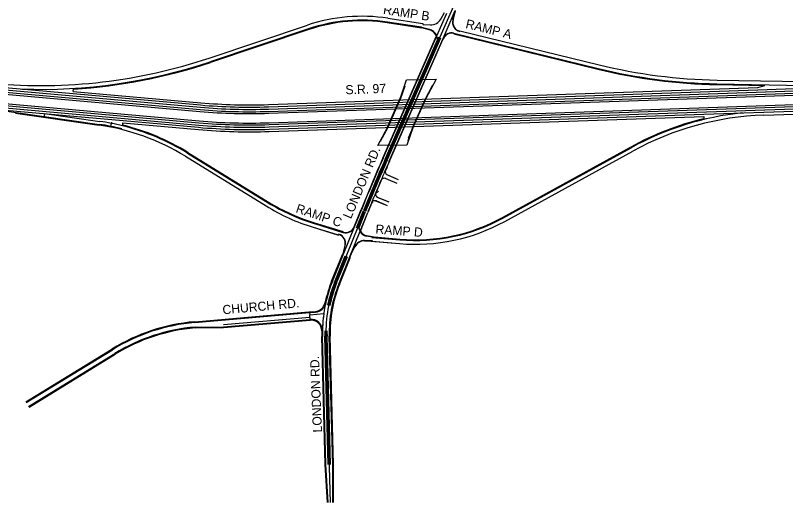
# Model space of a CAD drawing. Extents: x 2315515 to 2326910, y 758186 to 762794.
# Drawn here: x 2318941 to 2323003, y 758186 to 760752 of the extents above; entities that cross this region are included whole.
import ezdxf

# ---------------------------------------------------------------- set-up
doc = ezdxf.new("R2010")
doc.units = 0
for name, color, linetype in [('_CIVIL_CONSTRUCTION', 7, 'Continuous'), ('Bridge_Abutment', 7, 'Continuous'), ('Bridge_Bearing', 7, 'Continuous'), ('Bridge_Deck', 7, 'Continuous'), ('Clipping_Shape', 7, 'Continuous'), ('Default', 7, 'Continuous'), ('Draft_Corr_Final', 7, 'Continuous'), ('Draft_Corr_Range_Final', 7, 'Continuous'), ('E_Terrain_Exterior', 7, 'Continuous'), ('Pavement Marking Yellow', 7, 'Continuous'), ('Road_Curb_Face', 7, 'Continuous'), ('TL_Base Extension Sub', 7, 'Continuous'), ('TL_End Condition Ditch In', 7, 'Continuous'), ('TL_End Condition Ditch Out', 7, 'Continuous'), ('TL_Pavement Centerline', 7, 'Continuous'), ('TL_Pavement Centerline Sub', 7, 'Continuous')]:
    doc.layers.add(name, color=color, linetype=linetype)

msp = doc.modelspace()

# ---------------------------------------------------------------- linework, layer by layer
at = {"layer": '_CIVIL_CONSTRUCTION'}
for p, q in [((2315524.7, 760646.8), (2319915.4, 760256.1)), ((2315518.5, 760577.1), (2319909.2, 760186.4)), ((2320276.5, 760246.3), (2324006, 760375.3)), ((2320278.9, 760176.4), (2324008.4, 760305.3))]:
    msp.add_line(p, q, dxfattribs=at)
for radius in [2931, 3001]:
    msp.add_arc((2320175.2, 763175.6), radius, 264.9144, 271.9805, dxfattribs=at)
at = {"layer": 'Bridge_Abutment'}
for p, q in [((2320970, 760308.5), (2320994, 760379.5)), ((2321103.2, 760313.3), (2321141.6, 760383.5)), ((2320904.4, 760159.2), (2320970, 760308.5)), ((2321037.2, 760163.2), (2321103.2, 760313.3)), ((2320866, 760089.1), (2320904.4, 760159.2)), ((2321013.2, 760092.1), (2321037.2, 760163.2))]:
    msp.add_line(p, q, dxfattribs=at)
at = {"layer": 'Bridge_Bearing'}
for p, q in [((2320994, 760379.5), (2320970, 760308.5)), ((2321141.6, 760383.5), (2321103.2, 760313.3)), ((2320904.4, 760159.2), (2320970, 760308.5)), ((2321037.2, 760163.2), (2321103.2, 760313.3)), ((2320866, 760089.1), (2320904.4, 760159.2)), ((2321013.2, 760092.1), (2321037.2, 760163.2))]:
    msp.add_line(p, q, dxfattribs=at)
at = {"layer": 'Bridge_Deck'}
for p, q in [((2320891.3, 760134.3), (2320977.7, 760331.1)), ((2320946.3, 760259.5), (2320966.8, 760306.2)), ((2321014.9, 760107.4), (2321107.7, 760318.6)), ((2321083.8, 760264.2), (2321104.3, 760311)), ((2320903.4, 760161.9), (2320924, 760208.7)), ((2321041, 760166.7), (2321061.5, 760213.4))]:
    msp.add_line(p, q, dxfattribs=at)
at = {"layer": 'Clipping_Shape'}
for p, q in [((2320969.1, 760308.8), (2320993.1, 760379.8)), ((2320903.6, 760159.7), (2320969.1, 760308.8)), ((2320865.1, 760089.5), (2320903.6, 760159.7))]:
    msp.add_line(p, q, dxfattribs=at)
msp.add_lwpolyline([(2320852.2, 760066.2), (2320904.3, 760161.4), (2320968.5, 760307.7), (2321003.8, 760411.9), (2321160.3, 760415.2), (2321103.4, 760311.5), (2321039.2, 760165.2), (2321006.2, 760067.6)], close=True, dxfattribs=at)
at = {"layer": 'Default'}
for p, q in [((2320896.6, 759992.2), (2321353.4, 761032.3)), ((2320896.6, 759992.2), (2321353.4, 761032.3)), ((2320896.6, 759992.2), (2321353.4, 761032.3)), ((2320840.7, 759815.8), (2320856, 759826.5)), ((2320820.4, 759766.7), (2320828.3, 759770.7)), ((2320629.4, 759343.1), (2320782.4, 759721.3)), ((2320629.4, 759343.1), (2320782.4, 759721.3)), ((2320629.4, 759343.1), (2320782.4, 759721.3)), ((2320602.3, 758186.1), (2320578.6, 759061.6)), ((2320602.3, 758186.1), (2320578.6, 759061.6)), ((2320602.3, 758186.1), (2320578.6, 759061.6))]:
    msp.add_line(p, q, dxfattribs=at)
for centre, radius, start, end in [((2330052.7, 755971.5), 10000, 156.2923, 157.9768), ((2330052.7, 755971.5), 10000, 156.2923, 157.9768), ((2330052.7, 755971.5), 10000, 156.2923, 157.9768), ((2321278.3, 759080.6), 700, 157.9768, 181.5499), ((2321278.3, 759080.6), 700, 157.9768, 181.5499), ((2321278.3, 759080.6), 700, 157.9768, 181.5499)]:
    msp.add_arc(centre, radius, start, end, dxfattribs=at)
at = {"layer": 'Draft_Corr_Final'}
for p, q in [((2315523.8, 760636.9), (2319914.5, 760246.1)), ((2315519.4, 760587.1), (2319910, 760196.3)), ((2320276.8, 760236.3), (2324006.3, 760365.3)), ((2320278.5, 760186.3), (2324008.1, 760315.3))]:
    msp.add_line(p, q, dxfattribs=at)
for radius in [2941, 2991]:
    msp.add_arc((2320175.2, 763175.6), radius, 264.9144, 271.9805, dxfattribs=at)
at = {"layer": 'Draft_Corr_Range_Final'}
for p, q in [((2315525.8, 760658.8), (2319916.4, 760268.1)), ((2315517.4, 760565.2), (2319908.1, 760174.4)), ((2320276.1, 760258.3), (2324005.6, 760387.3)), ((2320279.3, 760164.4), (2324008.8, 760293.3)), ((2320037.8, 759122.9), (2320494.2, 759162.3))]:
    msp.add_line(p, q, dxfattribs=at)
for radius in [2919, 3013]:
    msp.add_arc((2320175.2, 763175.6), radius, 264.9144, 271.9805, dxfattribs=at)
at = {"layer": 'E_Terrain_Exterior'}
for p, q in [((2321184.8, 760732.9), (2321204.5, 760767.9)), ((2321248.3, 760728.3), (2321261, 760777.3)), ((2321083.3, 760689.3), (2320902.9, 760716.9)), ((2321083.3, 760689.3), (2321122.2, 760679.3)), ((2321083.3, 760689.3), (2321122.2, 760679.3)), ((2321089.2, 760704.6), (2321129.4, 760702.5)), ((2320487.5, 760681.4), (2319968.8, 760508)), ((2321253.9, 760658.1), (2322014.4, 760472.4)), ((2321253.9, 760658.1), (2322014.4, 760472.4)), ((2320880.1, 759999.4), (2321163, 760643.5)), ((2320880.1, 759999.4), (2321163, 760643.5)), ((2320913.1, 759984.9), (2321196.2, 760629.7)), ((2320913.1, 759984.9), (2321196.2, 760629.7)), ((2322641, 760391.4), (2323391.1, 760378)), ((2322641, 760391.4), (2323391.1, 760378)), ((2319094.8, 760234.8), (2319386.5, 760193.3)), ((2321512.1, 759684), (2322187.7, 760054.5)), ((2321512.1, 759684), (2322187.7, 760054.5)), ((2319848.5, 760026.7), (2320274.1, 759765)), ((2320894.2, 759915.3), (2320960, 759887.1)), ((2320886.3, 759897), (2320952.1, 759868.7)), ((2320895.2, 759893.2), (2320952.1, 759868.7)), ((2320903, 759911.6), (2320960, 759887.1)), ((2320844.8, 759796.2), (2320910.1, 759769.1)), ((2320852.8, 759792.8), (2320910.1, 759769.1)), ((2320837.1, 759777.7), (2320902.4, 759750.7)), ((2320845.2, 759774.4), (2320902.4, 759750.7)), ((2320729.3, 759638), (2320765.7, 759728)), ((2320729.3, 759638), (2320765.7, 759728)), ((2320758.7, 759614.8), (2320799.1, 759714.5)), ((2320758.7, 759614.8), (2320799.1, 759714.5)), ((2320517.6, 759655.1), (2320668.3, 759608.9)), ((2320833, 759581.8), (2320793.5, 759589.3)), ((2320833, 759581.8), (2320793.5, 759589.3)), ((2320782.8, 759566.1), (2320823, 759566.6)), ((2320820.8, 759582.8), (2320968.7, 759569.9)), ((2320833, 759581.8), (2320968.7, 759569.9)), ((2320612.7, 759349.8), (2320680.2, 759516.6)), ((2320669.6, 759490.4), (2320680.9, 759539.8)), ((2320711.7, 759498.5), (2320730.4, 759534)), ((2320612.7, 759349.8), (2320669.6, 759490.4)), ((2320646.1, 759336.3), (2320712.8, 759501.1)), ((2320646.1, 759336.3), (2320711.7, 759498.5)), ((2319886.9, 759134), (2320492.1, 759186.2)), ((2320492.1, 759186.2), (2320523.9, 759189)), ((2320492.1, 759186.2), (2320523.9, 759189)), ((2320492.1, 759186.2), (2320493.2, 759174.3)), ((2320038.8, 759111), (2320495.2, 759150.3)), ((2320038.8, 759111), (2320495.2, 759150.3)), ((2320495.2, 759150.3), (2320493.2, 759174.3)), ((2319889, 759110.1), (2320038.8, 759111)), ((2320578.9, 758385.5), (2320560.6, 759061.2)), ((2320578.9, 758385.5), (2320560.6, 759061.2)), ((2320614.8, 758386.5), (2320596.6, 759062.1)), ((2320614.8, 758386.5), (2320596.6, 759062.1)), ((2318998.3, 758712.1), (2319452.4, 758990.9)), ((2319010.8, 758691.7), (2319464.9, 758970.4)), ((2320590.3, 758185.7), (2320578.9, 758385.5)), ((2320614.3, 758186.4), (2320614.8, 758386.5))]:
    msp.add_line(p, q, dxfattribs=at)
for centre, radius, start, end in [((2320768.6, 759840.1), 887, 81.2923, 108.4803), ((2321132.5, 760762.4), 60, 267.0029, 330.5817), ((2321296.6, 760715.6), 50, 165.3826, 256.2777), ((2321107.3, 760621.2), 60, 336.2923, 75.5817), ((2321107.3, 760621.2), 60, 21.8653, 75.5817), ((2321242, 760609.6), 50, 76.2777, 156.2923), ((2319073, 763188.3), 2826, 268.0003, 288.4803), ((2322691.8, 763246.9), 2856, 256.2777, 268.9805), ((2322691.8, 763246.9), 2856, 256.2777, 268.9805), ((2322940.8, 758681.5), 1566, 96.0766, 118.7415), ((2322940.8, 758681.5), 1566, 96.0766, 118.7415), ((2319216.9, 758999.3), 1206, 76.1189, 81.9144), ((2319216.9, 758999.3), 1206, 58.4184, 76.1189), ((2330052.7, 755971.5), 10018, 156.2923, 157.9768), ((2330052.7, 755971.5), 10018, 156.2923, 157.9768), ((2330052.7, 755971.5), 9982, 156.2923, 156.67031), ((2330052.7, 755971.5), 9982, 156.2923, 156.58701), ((2320910.9, 759929.9), 20, 156.587, 246.7596), ((2330052.7, 755971.5), 9982, 156.82209, 157.38068), ((2330052.7, 755971.5), 9982, 156.93209, 157.32833), ((2320887.3, 759874.8), 20, 66.7596, 156.9321), ((2320860.5, 759811.3), 20, 157.3283, 247.5009), ((2320826.1, 760662.9), 1054, 238.4184, 252.9768), ((2330052.7, 755971.5), 9982, 157.60715, 157.9768), ((2330052.7, 755971.5), 9982, 157.67342, 157.9768), ((2320837.5, 759755.9), 20, 67.5009, 157.6734), ((2321052.4, 760522.2), 956, 264.9768, 298.7415), ((2321052.4, 760522.2), 956, 264.9768, 298.7415), ((2320682.9, 759656.8), 50, 252.9768, 337.9768), ((2320802.8, 759638.4), 50, 157.9768, 259.2662), ((2320632.2, 759551), 50, 347.0671, 72.9768), ((2320802.8, 759638.4), 50, 208.185, 259.2662), ((2320783.5, 759506.1), 60, 90.6874, 152.2662), ((2321278.3, 759080.6), 718, 157.9768, 168.1459), ((2321278.3, 759080.6), 718, 157.9768, 168.1459), ((2321278.3, 759080.6), 682, 157.9768, 181.5499), ((2321278.3, 759080.6), 682, 157.9768, 181.5499), ((2320518.7, 759248.7), 60, 274.9294, 347.5179), ((2320518.7, 759248.7), 60, 274.9294, 347.5179), ((2320500.4, 759090.6), 60, 359.264, 94.9294), ((2321278.3, 759080.6), 718, 172.8394, 181.5499), ((2319972.3, 758143.7), 994, 94.9294, 121.5395), ((2319972.3, 758143.7), 970, 94.9662, 121.5395), ((2321278.3, 759080.6), 718, 179.264, 181.5499)]:
    msp.add_arc(centre, radius, start, end, dxfattribs=at)
msp.add_open_spline([(2319888.4, 759110.1), (2319888.4, 759110.1), (2319888.4, 759110.1), (2319888.4, 759110.1), (2319888.5, 759110.1), (2319888.5, 759110.1), (2319888.5, 759110.1), (2319888.6, 759110.1), (2319888.6, 759110.1), (2319888.6, 759110.1), (2319888.6, 759110.1), (2319888.7, 759110.1), (2319888.7, 759110.1), (2319888.7, 759110.1), (2319888.8, 759110.1), (2319888.8, 759110.1), (2319888.8, 759110.1), (2319888.9, 759110.1), (2319888.9, 759110.1), (2319888.9, 759110.1), (2319889, 759110.1), (2319889, 759110.1), (2319889, 759110.1)], degree=3, dxfattribs=at)
at = {"layer": 'Pavement Marking Yellow'}
for p, q in [((2320891.1, 759994.6), (2321174, 760638.7)), ((2320902.1, 759989.8), (2321185, 760633.9)), ((2320740.4, 759633.5), (2320776.8, 759723.5)), ((2320751.5, 759628.9), (2320787.9, 759719)), ((2320623.8, 759345.3), (2320680.7, 759485.9)), ((2320635, 759340.8), (2320691.8, 759481.4)), ((2320590.9, 758385.8), (2320572.6, 759061.5)), ((2320602.9, 758386.2), (2320584.6, 759061.8))]:
    msp.add_line(p, q, dxfattribs=at)
for centre, radius, start, end in [((2330052.7, 755971.5), 10006, 156.2923, 157.9768), ((2330052.7, 755971.5), 9994, 156.2923, 157.9768), ((2321278.3, 759080.6), 706, 157.9768, 168.1459), ((2321278.3, 759080.6), 694, 157.9768, 168.1459), ((2321278.3, 759080.6), 706, 179.264, 181.5499), ((2321278.3, 759080.6), 694, 179.264, 181.5499)]:
    msp.add_arc(centre, radius, start, end, dxfattribs=at)
at = {"layer": 'Road_Curb_Face'}
for p, q in [((2321249.7, 760727.9), (2321262.5, 760776.9)), ((2321249.7, 760727.9), (2321262.5, 760776.8)), ((2321082.9, 760687.8), (2321121.9, 760677.8)), ((2321083.1, 760687.8), (2321121.9, 760677.8)), ((2320878.8, 760000), (2321161.6, 760644.1)), ((2320878.8, 760000), (2321161.4, 760643.5)), ((2320914.5, 759984.3), (2321197.6, 760629.1)), ((2320727.9, 759638.6), (2320764.3, 759728.6)), ((2320727.9, 759638.6), (2320764.3, 759728.6)), ((2320760.1, 759614.2), (2320800.5, 759714)), ((2320760.4, 759614.9), (2320800.5, 759714)), ((2320833.3, 759583.3), (2320793.8, 759590.7)), ((2320833.3, 759583.3), (2320793.8, 759590.7)), ((2320782.8, 759564.6), (2320823, 759565.1)), ((2320668.1, 759490.8), (2320679.5, 759540.1)), ((2320668.2, 759491), (2320679.5, 759540.1)), ((2320713, 759497.8), (2320731.7, 759533.3)), ((2320704.4, 759476.4), (2320713, 759497.8))]:
    msp.add_line(p, q, dxfattribs=at)
for centre, radius, start, end in [((2321296.6, 760715.6), 48.5, 165.3826, 256.2777), ((2321296.6, 760715.6), 48.5, 165.3826, 256.2777), ((2321107.3, 760621.2), 58.5, 23.8009, 75.5817), ((2321107.3, 760621.2), 58.5, 22.4792, 75.5817), ((2321242, 760609.6), 48.5, 76.2777, 156.2923), ((2330052.7, 755971.5), 10019.5, 156.2923, 157.9768), ((2330052.7, 755971.5), 10019.5, 156.2923, 157.9768), ((2330052.7, 755971.5), 9980.5, 156.2923, 156.58701), ((2330052.7, 755971.5), 9980.5, 156.93209, 157.33984), ((2330052.7, 755971.5), 9980.5, 157.66192, 157.9768), ((2330052.7, 755971.5), 9980.5, 157.66192, 157.9768), ((2320682.9, 759656.8), 48.5, 252.9768, 337.9768), ((2320632.2, 759551), 48.5, 347.0671, 72.9768), ((2320632.2, 759551), 48.5, 347.0671, 72.9768), ((2320802.8, 759638.4), 48.5, 209.0103, 259.2662), ((2320802.8, 759638.4), 48.5, 212.6887, 259.2662), ((2320783.5, 759506.1), 58.5, 90.6874, 152.2662)]:
    msp.add_arc(centre, radius, start, end, dxfattribs=at)
at = {"layer": 'TL_Base Extension Sub'}
for p, q in [((2319245.5, 760339.8), (2319917.5, 760280)), ((2320275.6, 760270.3), (2322857, 760359.6)), ((2320279.7, 760152.4), (2322571.6, 760231.6)), ((2319509.3, 760197.9), (2319907, 760162.5))]:
    msp.add_line(p, q, dxfattribs=at)
for radius in [2907, 3025]:
    msp.add_arc((2320175.2, 763175.6), radius, 264.9144, 271.9805, dxfattribs=at)
at = {"layer": 'TL_End Condition Ditch In'}
for p, q in [((2321196.2, 760629.7), (2321261, 760777.3)), ((2321163, 760643.5), (2321215.5, 760763.1)), ((2318013.8, 760449.4), (2319245.5, 760339.8)), ((2322857, 760359.6), (2323696.6, 760388.6)), ((2318790.3, 760261.9), (2319509.3, 760197.9)), ((2322571.6, 760231.6), (2323686.3, 760270.2)), ((2320669.6, 759490.4), (2320729.3, 759638)), ((2320703, 759476.9), (2320758.7, 759614.8))]:
    msp.add_line(p, q, dxfattribs=at)
for centre, radius, start, end in [((2330052.7, 755971.5), 9982, 156.58701, 156.93209), ((2330052.7, 755971.5), 9982, 157.33984, 157.66192), ((2321278.3, 759080.6), 718, 167.5179, 179.264)]:
    msp.add_arc(centre, radius, start, end, dxfattribs=at)
at = {"layer": 'TL_End Condition Ditch Out'}
for p, q in [((2318790.3, 760261.9), (2319092.5, 760218.9)), ((2319094.8, 760234.8), (2319092.5, 760218.9)), ((2319092.5, 760218.9), (2319384.3, 760177.5)), ((2319444.7, 760167.3), (2319449, 760190)), ((2320493.2, 759174.3), (2320567.3, 759180.7))]:
    msp.add_line(p, q, dxfattribs=at)
msp.add_arc((2319216.9, 758999.3), 1190, 76.1189, 81.9144, dxfattribs=at)
at = {"layer": 'TL_Pavement Centerline'}
for p, q in [((2320275.2, 760282.3), (2322856.6, 760371.6)), ((2319246.6, 760351.8), (2319918.6, 760292)), ((2320280.1, 760140.4), (2322572, 760219.6)), ((2319508.3, 760185.9), (2319906, 760150.5))]:
    msp.add_line(p, q, dxfattribs=at)
for radius in [2895, 3037]:
    msp.add_arc((2320175.2, 763175.6), radius, 264.9144, 271.9805, dxfattribs=at)
at = {"layer": 'TL_Pavement Centerline Sub'}
for p, q in [((2320905.9, 760736.7), (2321089.8, 760708.5)), ((2319962.4, 760527), (2320481.1, 760700.4)), ((2321082.7, 760685.3), (2320902.3, 760713)), ((2321089.8, 760708.5), (2321089.2, 760704.6)), ((2320488.7, 760677.6), (2319970, 760504.2)), ((2321253.9, 760658.1), (2321252.9, 760654.3)), ((2321252.9, 760654.3), (2322013.4, 760468.6)), ((2321284.8, 760667.1), (2321285.7, 760671)), ((2321285.7, 760671), (2322019.1, 760491.9)), ((2322641.4, 760411.4), (2323583.4, 760394.6)), ((2319246.6, 760351.8), (2319247.7, 760363.7)), ((2322641, 760387.4), (2322893.8, 760382.9)), ((2322856.6, 760371.6), (2322893.8, 760382.9)), ((2322887.3, 760226.5), (2323387, 760243.8)), ((2322887.3, 760226.5), (2323387, 760243.8)), ((2318941.1, 760236.4), (2319383.7, 760173.5)), ((2318941.1, 760236.4), (2319383.7, 760173.5)), ((2322572, 760219.6), (2322572.4, 760207.6)), ((2319507.2, 760174), (2319508.3, 760185.9)), ((2321510.1, 759687.5), (2322185.8, 760058)), ((2321521.7, 759666.4), (2322197.4, 760037)), ((2321521.7, 759666.4), (2322197.4, 760037)), ((2319838, 760009.6), (2320263.7, 759748)), ((2319838, 760009.6), (2320263.7, 759748)), ((2319850.6, 760030.1), (2320276.2, 759768.4)), ((2320511.7, 759636), (2320638.4, 759597.2)), ((2320511.7, 759636), (2320645.7, 759595)), ((2320518.7, 759658.9), (2320669.5, 759612.8)), ((2320646.8, 759598.8), (2320645.7, 759595)), ((2320815.4, 759563.2), (2320966.9, 759549.9)), ((2320823.2, 759566.6), (2320822.8, 759562.6)), ((2320822.8, 759562.6), (2320966.9, 759549.9)), ((2320833.4, 759581.7), (2320833.7, 759585.7)), ((2320833.7, 759585.7), (2320969, 759573.8)), ((2320609, 759351.3), (2320665.9, 759491.9)), ((2320649.8, 759334.8), (2320706.7, 759475.4)), ((2320669.6, 759490.4), (2320665.9, 759491.9)), ((2320703, 759476.9), (2320706.7, 759475.4)), ((2319886.6, 759138), (2320523.5, 759192.9)), ((2319886.6, 759138), (2320507.4, 759191.5)), ((2320039, 759107), (2320495.6, 759146.4)), ((2320039.2, 759107), (2320495.6, 759146.4)), ((2319888.5, 759106.1), (2320039, 759107)), ((2319889, 759106.1), (2320038.9, 759107)), ((2320574.9, 758385.4), (2320556.6, 759061)), ((2320574.9, 758385.3), (2320556.6, 759061)), ((2320618.8, 758386.6), (2320600.6, 759062.2)), ((2318996.2, 758715.5), (2319450.3, 758994.3)), ((2318996.2, 758715.5), (2319450.3, 758994.3)), ((2319012.9, 758688.3), (2319467, 758967)), ((2319012.9, 758688.3), (2319467, 758967)), ((2320586.3, 758185.5), (2320574.9, 758385.3)), ((2320586.3, 758185.5), (2320574.9, 758385.3)), ((2320618.3, 758186.4), (2320618.8, 758386.5)), ((2320618.3, 758186.4), (2320618.8, 758386.5))]:
    msp.add_line(p, q, dxfattribs=at)
for centre, radius, start, end in [((2320768.6, 759840.1), 907, 81.2923, 108.4803), ((2320768.6, 759840.1), 883, 81.2923, 108.4803), ((2319073, 763188.3), 2806, 264.9144, 288.4803), ((2319073, 763188.3), 2830, 273.5389, 288.4803), ((2322691.8, 763246.9), 2836, 256.2777, 268.9805), ((2322691.8, 763246.9), 2860, 256.2777, 268.9805), ((2322940.8, 758681.5), 1570, 103.5684, 118.7415), ((2322940.8, 758681.5), 1546, 91.9805, 118.7415), ((2322940.8, 758681.5), 1546, 91.9805, 118.7415), ((2319216.9, 758999.3), 1186, 58.4184, 81.9144), ((2319216.9, 758999.3), 1186, 58.4184, 81.9144), ((2319216.9, 758999.3), 1210, 58.4184, 76.1189), ((2320826.1, 760662.9), 1050, 238.4184, 252.9768), ((2320826.1, 760662.9), 1074, 238.4184, 252.9768), ((2320826.1, 760662.9), 1074, 238.4184, 252.9768), ((2321052.4, 760522.2), 952, 264.9768, 298.7415), ((2321052.4, 760522.2), 976, 264.9768, 298.7415), ((2321052.4, 760522.2), 976, 264.9768, 298.7415), ((2321278.3, 759080.6), 722, 157.9768, 167.5179), ((2321278.3, 759080.6), 678, 157.9768, 181.5499), ((2320518.7, 759248.7), 56, 274.9294, 347.5179), ((2320518.7, 759248.7), 56, 274.9294, 347.5179), ((2320500.4, 759090.6), 56, 359.264, 94.9294), ((2319972.3, 758143.7), 998, 94.9294, 121.5395), ((2319972.3, 758143.7), 998, 94.9294, 121.5395), ((2319972.3, 758143.7), 966, 94.9662, 121.5395), ((2319972.3, 758143.7), 966, 94.9761, 121.5395), ((2321278.3, 759080.6), 722, 179.264, 181.5499), ((2321278.3, 759080.6), 722, 179.264, 181.5499)]:
    msp.add_arc(centre, radius, start, end, dxfattribs=at)

# ---------------------------------------------------------------- texts
at = {"layer": 'Default'}
for s, rotation, p in [('RAMP B', 351.3639, (2320878.3, 760760.2)), ('RAMP A', 346.2856, (2321312.1, 760686)), ('S.R. 97', 2.1074, (2320682.6, 760336.1)), ('LONDON RD.', 67.0887, (2320710.8, 759677)), ('RAMP C', 341.6007, (2320416.2, 759715)), ('RAMP D', 355.8776, (2320838.8, 759602.9)), ('CHURCH RD.', 5.3529, (2320035.5, 759176.6)), ('LONDON RD.', 92.2882, (2320558.2, 758555.9))]:
    msp.add_text(s, height=48, rotation=rotation, dxfattribs=at).set_placement(p)

doc.saveas('drawing.dxf')
